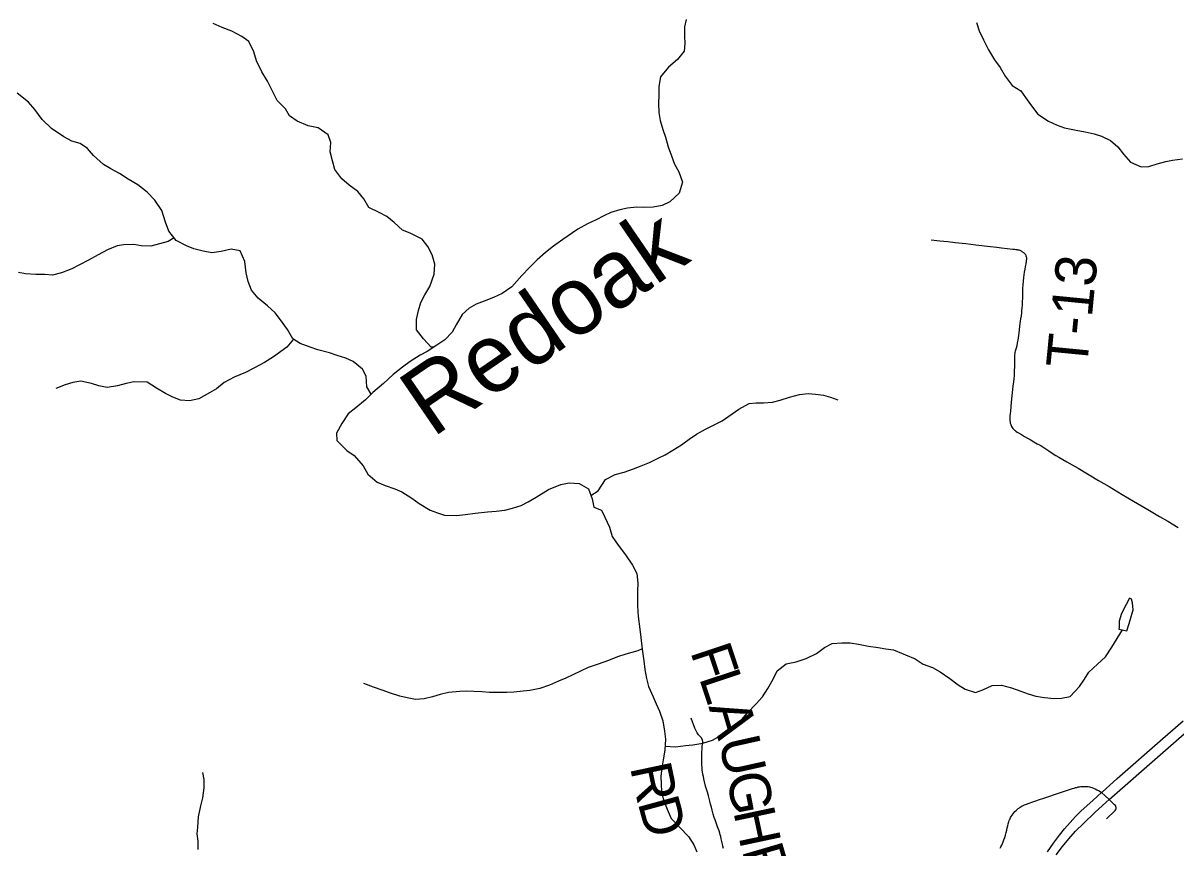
# Model space of a CAD drawing. Extents: x 1451455 to 1749751, y 218250 to 574981.
# Drawn here: x 1587271 to 1595698, y 286670 to 292701 of the extents above; entities that cross this region are included whole.
import ezdxf

# ---------------------------------------------------------------- set-up
doc = ezdxf.new("R2010")
doc.units = 0
for name, color, linetype in [('GM_X_County_Road', 7, 'Continuous'), ('GM_X_Minor_Lake', 7, 'Continuous'), ('GM_X_Minor_River', 7, 'Continuous'), ('GM_X_Minor_River_Text', 7, 'Continuous'), ('GM_X_Township_Road', 7, 'Continuous'), ('GM_X_Township_Road_Text', 7, 'Continuous'), ('GM_X_Township_ROW', 7, 'Continuous'), ('GM_X_US_Route', 7, 'Continuous')]:
    doc.layers.add(name, color=color, linetype=linetype)

msp = doc.modelspace()

# ---------------------------------------------------------------- linework, layer by layer
at = {"layer": 'GM_X_County_Road'}
for points in [[(1594481.8, 286875.5), (1594483, 286878.7), (1594486.5, 286886.1), (1594490, 286892.2), (1594494.1, 286899), (1594500.4, 286909.1), (1594507.3, 286918.7), (1594513.8, 286927.3), (1594521.6, 286936.4), (1594529.5, 286944.7), (1594537.7, 286952.1), (1594545.5, 286958.2), (1594553.8, 286964.2), (1594560.3, 286968.6), (1594566.8, 286972.5), (1594574.6, 286976.8), (1594581.6, 286980.3), (1594591.1, 286984.2), (1594605.4, 286989.8), (1594625, 286997.2), (1594653, 287007.4), (1594674.9, 287015), (1594701.3, 287023.7), (1594731.7, 287033.6), (1594768.2, 287045.8), (1594811.1, 287060.6), (1594927.9, 287099.6), (1594942.2, 287104), (1594955.2, 287107.9), (1594965.2, 287110.9), (1594973.9, 287113.1), (1594983.9, 287115.7), (1594993.9, 287117.9), (1595003.4, 287119.1), (1595012.1, 287120), (1595021.6, 287120.5), (1595029.9, 287120.5), (1595039.9, 287120), (1595048.1, 287119.1), (1595056.8, 287118.3), (1595066.5, 287116.6), (1595074.2, 287114.4), (1595082.7, 287111.4), (1595095.5, 287107), (1595107.6, 287101.8), (1595120.7, 287095.7), (1595136.3, 287087.4), (1595154.5, 287075.3)], [(1595154.5, 287075.3), (1595181.8, 287051), (1595210.1, 287024.1)], [(1594413.1, 286667.3), (1594418.8, 286677.8), (1594424.9, 286690.3), (1594430.7, 286702.8), (1594436.1, 286715.5), (1594441.4, 286729.8), (1594447, 286745.9), (1594452.2, 286763.8), (1594457.4, 286783.2), (1594461.3, 286799.7), (1594465.2, 286816.7), (1594468.7, 286831.4), (1594472.6, 286847.5), (1594477, 286861.8), (1594480, 286870.9), (1594481.8, 286875.5)]]:
    msp.add_lwpolyline(points, dxfattribs=at)
at = {"layer": 'GM_X_Minor_Lake'}
for points in [[(1595339.9, 288258.4), (1595356.6, 288312.2), (1595385.9, 288409.9), (1595380.5, 288462.1), (1595372.9, 288490.2), (1595358.9, 288496.4), (1595334.4, 288450.7), (1595299.5, 288385.1), (1595282.7, 288327.2), (1595284.4, 288297.2)], [(1595284.4, 288297.2), (1595283.8, 288282.5), (1595279.9, 288270), (1595339.9, 288258.4)]]:
    msp.add_lwpolyline(points, dxfattribs=at)
at = {"layer": 'GM_X_Minor_River'}
for points in [[(1590272.1, 290331), (1590253.6, 290331.4), (1590198.3, 290392.2), (1590147.1, 290459), (1590146.1, 290533.1), (1590162.9, 290600.9), (1590179.7, 290658.8), (1590208.4, 290714.4), (1590245.2, 290776), (1590276.4, 290865.6), (1590281.3, 290937.6), (1590262.2, 291006), (1590230.9, 291066.5), (1590189.6, 291121), (1590102, 291164.3), (1590044.3, 291187.1), (1589984.9, 291243.9), (1589929.4, 291286.7), (1589873.7, 291315.5), (1589798.1, 291352.6), (1589762.9, 291417.1), (1589717.5, 291469.8), (1589654.1, 291516.6), (1589602.6, 291563.4), (1589551.4, 291630.1), (1589532.2, 291694.4), (1589517, 291760.7), (1589519.9, 291828.7), (1589502.6, 291885), (1589429.2, 291936), (1589355.3, 291949.1), (1589275.7, 291984.2), (1589218.1, 292023), (1589188.7, 292073.4), (1589129.4, 292134.3), (1589092.3, 292208.8), (1589057.2, 292275.4), (1589016, 292344), (1588977, 292424.6), (1588957.8, 292490.9), (1588922.7, 292567.4), (1588871.1, 292602.1), (1588797.6, 292643.2), (1588725.8, 292668.1), (1588660.2, 292697.1)], [(1592117.7, 292728.4), (1592105, 292674.5), (1592106.2, 292606.5), (1592109.5, 292552.4), (1592102.8, 292496.4), (1592055.9, 292435), (1591989.1, 292377.9), (1591930.2, 292308.6), (1591919.3, 292236.7), (1591918.4, 292170.6), (1591915.7, 292114.6), (1591918.9, 292046.5), (1591928.1, 291988.3), (1591947.3, 291924), (1591966.6, 291867.7), (1591987.8, 291797.4), (1592010.9, 291731), (1592034.2, 291670.6), (1592065.5, 291614.1), (1592092.6, 291537.7), (1592067.5, 291458), (1591998.7, 291394.8), (1591942.3, 291367.6), (1591876.1, 291354.5), (1591808, 291353.4), (1591757.9, 291354.1), (1591689.8, 291349), (1591633.6, 291335.7), (1591567.3, 291316.6), (1591516.9, 291291.3), (1591460.5, 291262), (1591396.1, 291232.9), (1591325.5, 291193.8), (1591216.5, 291119.2), (1591147.8, 291070.1), (1591091.2, 291024.8), (1591028.4, 290969.6), (1590973.6, 290914.3), (1590916.8, 290855), (1590843.8, 290773.9), (1590773, 290722.8), (1590710.6, 290693.6), (1590642.2, 290668.5), (1590583.9, 290645.3), (1590531.5, 290616), (1590480.8, 290570.6), (1590437.8, 290495.1), (1590409.1, 290441.5), (1590354.4, 290384.1), (1590295.8, 290346.9), (1590225.2, 290299.8), (1590172.8, 290272.5), (1590102.1, 290227.4), (1590045.6, 290186.1), (1589976.8, 290131), (1589905.9, 290065.9), (1589829, 290000.8), (1589774.3, 289947.5), (1589703.5, 289888.4), (1589648.9, 289843.1), (1589601.9, 289773.7), (1589563, 289702.1), (1589564.3, 289648), (1589637.5, 289575)], [(1594241.3, 292705.7), (1594260.6, 292643.4), (1594291.8, 292578.9), (1594328.9, 292506.4), (1594372, 292433.7), (1594413.3, 292377.1), (1594450.5, 292312.5), (1594501.7, 292243.8), (1594565.3, 292206.9), (1594598.7, 292156.4), (1594636.1, 292105.9), (1594689.2, 292035.1), (1594766.6, 291984), (1594830.3, 291955.1), (1594884.1, 291936.4), (1594968, 291919.2), (1595035.9, 291906.3), (1595101.7, 291891.4), (1595153.6, 291874.7), (1595219.2, 291843.8), (1595272.7, 291797), (1595316, 291742.4), (1595365.3, 291683.6), (1595443, 291650.6), (1595499.1, 291653.8), (1595561.3, 291671), (1595623.6, 291690.2), (1595673.8, 291699.5), (1595746, 291708.5)], [(1589815.9, 289988), (1589783.5, 290041.5), (1589780.5, 290119.6), (1589753.1, 290170), (1589683.8, 290227), (1589630, 290251.8), (1589566.2, 290270.6), (1589510.4, 290289.4), (1589426.6, 290312.6), (1589370.8, 290331.3), (1589297.1, 290358.4), (1589243.5, 290393.1), (1589204.3, 290459.7), (1589153.1, 290530.5), (1589113.7, 290583), (1589058.3, 290633.8), (1588989, 290690.8), (1588941.7, 290749.5), (1588916.5, 290811.9), (1588903.2, 290874.2), (1588892.3, 290958.4), (1588859.3, 291036.9), (1588793.3, 291047.8), (1588719.1, 291030.8), (1588650.9, 291021.7), (1588587, 291034.6), (1588519.1, 291049.5), (1588465.3, 291072.2), (1588389.8, 291111.3), (1588336.6, 291180.1), (1588313.4, 291244.5), (1588286.5, 291330.9), (1588235.4, 291407.6), (1588178.1, 291464.5), (1588110.7, 291519.4), (1588039.1, 291560.4), (1587975.6, 291601.3), (1587914, 291636.2), (1587858.3, 291667), (1587787.1, 291732), (1587741.7, 291784.6), (1587688.1, 291821.4), (1587628.3, 291838.2), (1587570.6, 291869), (1587479.3, 291930.3), (1587410.1, 291997.3), (1587357, 292070), (1587311.6, 292122.7), (1587228.4, 292189.9)], [(1588375.1, 291130.3), (1588331.6, 291104.1), (1588205.1, 291069.7), (1588135, 291072.7), (1588081.1, 291083.4), (1588009, 291080.4), (1587958.9, 291073), (1587888.5, 291044), (1587819.9, 291006.8), (1587749.4, 290967.8), (1587684.9, 290934.6), (1587628.5, 290905.3), (1587552, 290874.3), (1587487.7, 290857.2), (1587431.7, 290861.9), (1587363.7, 290862.8), (1587289.7, 290867.8), (1587237.8, 290878.5)], [(1589248.7, 290389.7), (1589200.6, 290331.6), (1589101.7, 290260.9), (1589037.1, 290219.7), (1588958.5, 290178.8), (1588898, 290145.5), (1588815.5, 290112.6), (1588741, 290073.6), (1588684.3, 290026.3), (1588633.9, 289996.9), (1588557.3, 289953.9), (1588487, 289938.8), (1588423, 289943.7), (1588367.3, 289966.5), (1588311.5, 289993.3), (1588246, 290032.2), (1588178.5, 290075.1), (1588084.4, 290078.4), (1588024.2, 290065.2), (1587961.9, 290048), (1587885.7, 290037), (1587825.8, 290047.8), (1587772, 290066.6), (1587694.1, 290083.6), (1587635.9, 290072.4), (1587579.7, 290055.1), (1587511.3, 290030)], [(1591421.5, 289246.9), (1591475.4, 289281.9), (1591528.5, 289365.2), (1591599, 289400.3), (1591665.3, 289417.4), (1591733.7, 289442.5), (1591790, 289463.8), (1591850.4, 289489), (1591912.8, 289520.2), (1591965.2, 289545.5), (1592021.7, 289578.8), (1592084.2, 289618), (1592140.8, 289659.2), (1592193.3, 289696.6), (1592259.8, 289731.7), (1592312.2, 289759), (1592380.7, 289794.1), (1592431.2, 289827.5), (1592503.9, 289878.5), (1592578.5, 289919.6), (1592630.6, 289924.9), (1592682.6, 289924.2), (1592748.8, 289929.3), (1592805, 289944.5), (1592873.3, 289965.6), (1592945.7, 289986.7), (1593009.8, 289993.8), (1593063.8, 289989.1), (1593121.7, 289980.3), (1593173.6, 289965.6), (1593227.4, 289946.8)], [(1589637.5, 289575), (1589691.1, 289540.2), (1589756.2, 289463.3), (1589791.4, 289402.8), (1589858.7, 289343.8), (1589918.5, 289321), (1589988.3, 289296), (1590040, 289273.3), (1590113.5, 289228.2), (1590167.1, 289187.5), (1590246.5, 289140.3), (1590300.3, 289119.6), (1590352.2, 289102.9), (1590440.2, 289101.7), (1590506.4, 289108.8), (1590576.5, 289117.9), (1590666.7, 289126.6), (1590728.9, 289131.8), (1590793, 289141), (1590849.2, 289154.2), (1590911.5, 289173.4), (1590963.9, 289200.7), (1591022.4, 289236), (1591111.2, 289290.8), (1591201.8, 289327.6), (1591262, 289338.8), (1591336, 289333.8), (1591403.5, 289294.9), (1591430.6, 289222.4), (1591443.9, 289162.2), (1591499.7, 289139.4), (1591525, 289089), (1591558.1, 289014.5), (1591577.3, 288946.1), (1591620.5, 288883.5), (1591673.7, 288812.7), (1591726.8, 288737.9), (1591758, 288677.4), (1591765.2, 288607.2), (1591762.5, 288551.2), (1591763.7, 288495.1), (1591763, 288439.1), (1591768.1, 288363), (1591778.9, 288268.7), (1591786.1, 288208.5), (1591797.1, 288124.3), (1591810, 288038), (1591817.2, 287973.9), (1591828.4, 287909.7), (1591843.7, 287849.4), (1591876.7, 287774.8), (1591900.1, 287724.5), (1591923.5, 287670.1), (1591946.6, 287599.7), (1591959.6, 287523.5), (1591966.9, 287465.3), (1591961.9, 287385.3), (1591951, 287315.3), (1591940.3, 287255.4), (1591933.4, 287191.5), (1591934.8, 287137.4), (1591938.1, 287083.3), (1591953.3, 287019), (1591980.5, 286952.5), (1592007.7, 286886.1), (1592136.1, 286754.2), (1592175.4, 286693.6), (1592196.7, 286641.3)], [(1591963.7, 287414.1), (1592040.3, 287408.2), (1592114.5, 287419.2), (1592166.6, 287424.5), (1592240.8, 287435.5), (1592311.1, 287458.6), (1592389.8, 287501.6), (1592452.3, 287542.8), (1592511, 287592), (1592565.9, 287657.4), (1592628.8, 287722.6), (1592675.4, 287774), (1592714.3, 287835.5), (1592755.2, 287903.1), (1592784, 287964.8), (1592848.7, 288015.9), (1592922.9, 288030.9), (1592995.3, 288056), (1593069.8, 288093), (1593128.4, 288136.3), (1593184.9, 288165.5), (1593255, 288170.6), (1593317, 288169.7), (1593379, 288160.9), (1593450.8, 288145.9), (1593520.8, 288134.9), (1593578.7, 288126.1), (1593632.6, 288117.4), (1593722.3, 288082.1), (1593792, 288053.1), (1593851.5, 288014.3), (1593919.3, 287989.3), (1593974.9, 287956.6), (1594044.4, 287909.6), (1594105.8, 287862.7), (1594157.5, 287830), (1594233.2, 287806.9), (1594287.5, 287826.2), (1594356, 287857.3), (1594422.1, 287860.4), (1594495.9, 287841.4), (1594563.7, 287816.4), (1594617.4, 287795.7), (1594673.3, 287780.9), (1594737.2, 287770), (1594809.2, 287763), (1594861.3, 287764.3), (1594925.5, 287777.5), (1594992.5, 287850.6), (1595029.2, 287904.2), (1595061.9, 287955.8), (1595124.6, 288013), (1595183.4, 288068.3), (1595230.3, 288137.8), (1595308.5, 288264.5)], [(1591797, 288125.1), (1591764.9, 288110.7), (1591678.5, 288085.9), (1591616.2, 288066.7), (1591549.8, 288041.6), (1591475.4, 288014.5), (1591403, 287989.5), (1591350.7, 287966.2), (1591290.3, 287937), (1591239.9, 287911.6), (1591185.6, 287888.3), (1591119.2, 287861.2), (1591048.8, 287836.1), (1590976.5, 287821.1), (1590926.4, 287815.8), (1590858.3, 287808.7), (1590808.2, 287807.3), (1590750.1, 287806.1), (1590680.1, 287807.1), (1590624.1, 287811.8), (1590566.1, 287814.6), (1590514, 287815.3), (1590464, 287814), (1590381.8, 287807.1), (1590319.6, 287791.9), (1590263.3, 287774.7), (1590203.1, 287759.5), (1590139, 287756.3), (1590079, 287767.1), (1590025.1, 287779.9), (1589957.4, 287802.8), (1589895.6, 287823.7), (1589831.8, 287844.6), (1589762.1, 287873.5)], [(1588551.7, 286658.4), (1588550.4, 286720.5), (1588545.1, 286772.7), (1588547.7, 286822.7), (1588554.7, 286896.7), (1588569.7, 286978.6), (1588584.5, 287036.4), (1588595.4, 287110.4), (1588596.2, 287170.4), (1588584.8, 287220.6)]]:
    msp.add_lwpolyline(points, dxfattribs=at)
at = {"layer": 'GM_X_Township_Road'}
for points in [[(1594601.4, 290946), (1594600.5, 290941), (1594597, 290921.6), (1594593.1, 290901.3), (1594589.2, 290880.4), (1594586.2, 290860), (1594583.6, 290842.2), (1594581, 290814), (1594578.4, 290788), (1594577, 290762.3), (1594576.2, 290723.7), (1594575.8, 290690.2), (1594574.9, 290664.7), (1594574, 290641.3), (1594572.3, 290616.1), (1594570.6, 290598.7), (1594568.4, 290583.1), (1594565.8, 290560.1), (1594562.8, 290538), (1594558.4, 290505.8), (1594555.4, 290484.2), (1594551.9, 290457.7), (1594548.8, 290435.5), (1594546.3, 290416.4), (1594544.1, 290398.7), (1594541.5, 290382.2), (1594538.4, 290363.5), (1594534.1, 290340.9), (1594529.8, 290323.6), (1594524.1, 290303.2), (1594521.5, 290293.2), (1594520.2, 290285), (1594519.4, 290275.8), (1594518.9, 290256.7), (1594518.9, 290217.2), (1594518.6, 290199.2), (1594518, 290185.5), (1594517, 290163.2), (1594515.8, 290140.3), (1594514.9, 290123.9), (1594512.9, 290101.1), (1594510.2, 290077.9), (1594506.8, 290045.8), (1594493.7, 289929.5), (1594487.8, 289862.8), (1594485.9, 289844.8), (1594485.1, 289831.8), (1594484, 289820.4), (1594483.8, 289810.5), (1594483.8, 289802.7), (1594484, 289794.2), (1594485.5, 289783.6), (1594487.6, 289775), (1594490.6, 289765.9), (1594494.2, 289758), (1594497.5, 289751.2), (1594501.5, 289744.6), (1594506.8, 289737.6), (1594512, 289731.6), (1594517.6, 289725.9), (1594522.4, 289721.6), (1594528, 289717.1), (1594536.7, 289711.2), (1594546.5, 289704.9), (1594568.4, 289692.1), (1594592.3, 289678.2), (1594613.5, 289666), (1594631.8, 289655.6), (1594660, 289640), (1594684.7, 289625.7), (1594704.7, 289614), (1594724.6, 289601.8), (1594746.4, 289588.3), (1594769.8, 289573.6), (1594794.1, 289557.5), (1594820.6, 289540.6), (1594842.7, 289526.7), (1594870.9, 289510.2), (1594901.7, 289493.3), (1594940.3, 289472), (1594984.6, 289447.3), (1595132.6, 289357.4), (1595209.9, 289311.9), (1595305.8, 289255.4), (1595387.8, 289206), (1595493.3, 289143.5), (1595578.8, 289094), (1595638.7, 289058.4), (1595715.7, 289013.1)], [(1592390.4, 286666.6), (1592386.4, 286682.4), (1592383.1, 286696.8), (1592379.2, 286716.8), (1592374.8, 286736.3), (1592370.9, 286754.1), (1592367.9, 286765.4), (1592364, 286778.4), (1592358.4, 286795.4), (1592352.6, 286811.3), (1592347.9, 286823.6), (1592342.4, 286838.4), (1592336.6, 286854.8), (1592329.9, 286874.7), (1592323.7, 286893.2), (1592316.1, 286918.1), (1592308.2, 286946.1), (1592302.4, 286967.7), (1592296.9, 286989.1), (1592290.7, 287013.2), (1592285.4, 287032.8), (1592280.4, 287051.7), (1592273.3, 287077.5), (1592267.2, 287098.8), (1592262.4, 287114.8), (1592257.8, 287131.9), (1592252.4, 287153.4), (1592247.3, 287175.4), (1592243.8, 287193.4), (1592240.7, 287210.7), (1592238.1, 287226.4), (1592236.2, 287239.3), (1592234.6, 287258.4), (1592233.8, 287274.5), (1592233.2, 287288.1), (1592232.5, 287309.3), (1592232.4, 287329.5), (1592232.8, 287347.8), (1592233.8, 287372.2), (1592234.7, 287391.7), (1592236.3, 287411), (1592238.5, 287429.5), (1592239.4, 287439.9), (1592239, 287448.1), (1592238, 287456.5), (1592237, 287461.6), (1592228.6, 287476.7), (1592219.3, 287487.3), (1592209.3, 287497.6), (1592197.7, 287511.3), (1592181.6, 287545.3), (1592155.4, 287620)], [(1595191.2, 286883.5), (1595199.5, 286892.7), (1595244.7, 286934.9), (1595254.4, 286944.8), (1595258.6, 286950.9), (1595261.4, 286958.1), (1595261.6, 286965.9), (1595259.5, 286973.6), (1595255.4, 286980.2), (1595250.1, 286985.5), (1595232.6, 287002.8), (1595210.1, 287024.1)]]:
    msp.add_lwpolyline(points, dxfattribs=at)
at = {"layer": 'GM_X_Township_ROW'}
msp.add_lwpolyline([(1593909.4, 291116), (1593971.5, 291109.5), (1594029.8, 291103.1), (1594085.3, 291097), (1594162.1, 291088.8), (1594234.6, 291080.9), (1594342.7, 291068.3), (1594388.7, 291062.7), (1594424.3, 291058.6), (1594506.8, 291049.3), (1594518, 291048), (1594528.5, 291046.2), (1594536.7, 291044.9), (1594543.2, 291043.6), (1594548.8, 291042.3), (1594556.7, 291039.7), (1594561, 291038), (1594566.7, 291035.4), (1594572.3, 291032.3), (1594576.6, 291029.7), (1594580.1, 291027.1), (1594583.6, 291024.5), (1594587.5, 291021), (1594591.4, 291017.1), (1594594.4, 291013.6), (1594597.9, 291008.9), (1594600.1, 291004.6), (1594602.2, 290998.9), (1594603.9, 290993), (1594604.8, 290986.3), (1594605.3, 290979.4), (1594604.8, 290971.6), (1594604, 290964.6), (1594602.7, 290953.8), (1594601.4, 290946)], dxfattribs=at)
at = {"layer": 'GM_X_US_Route'}
for points in [[(1594759.5, 286640.8), (1594804, 286705.4), (1594846.9, 286763.2), (1594883.6, 286809.1), (1594924.3, 286856.1), (1594964.5, 286899), (1595006.4, 286940.4), (1595090.8, 287018), (1595154.5, 287075.3), (1595157.9, 287078.4), (1595268.8, 287178.1), (1595602.2, 287469.5), (1595750, 287599.5)], [(1594821.7, 286620.5), (1594867.9, 286680.3), (1594914.2, 286735.8), (1594965.2, 286791.7), (1595025.4, 286852.3), (1595106.1, 286929.4), (1595188.4, 287004.8), (1595210.1, 287024.1), (1595602.2, 287368.8), (1595777.7, 287521.9)]]:
    msp.add_lwpolyline(points, dxfattribs=at)

# ---------------------------------------------------------------- texts
at = {"layer": 'GM_X_Minor_River_Text'}
msp.add_text('Redoak', height=499.93, rotation=34.39039, dxfattribs=at).set_placement((1590262.3, 289664.5))
at = {"layer": 'GM_X_Township_Road_Text'}
for s, rotation, p in [('T-13', 84.42783, (1595046.6, 290167.8)), ('F', 288.43346, (1592146.3, 288106.3)), ('L', 288.38142, (1592210.3, 287914.4)), ('A', 286.32469, (1592280.2, 287704.2)), ('U', 282.59598, (1592353.1, 287455.8)), ('R', 281.9755, (1591707, 287261.2)), ('G', 281.13313, (1592410.3, 287200.1)), ('D', 285.2545, (1591762.5, 287002.3)), ('H', 281.9975, (1592462.3, 286936.3)), ('E', 286.32888, (1592523.2, 286654))]:
    msp.add_text(s, height=300, rotation=rotation, dxfattribs=at).set_placement(p)

doc.saveas('drawing.dxf')
